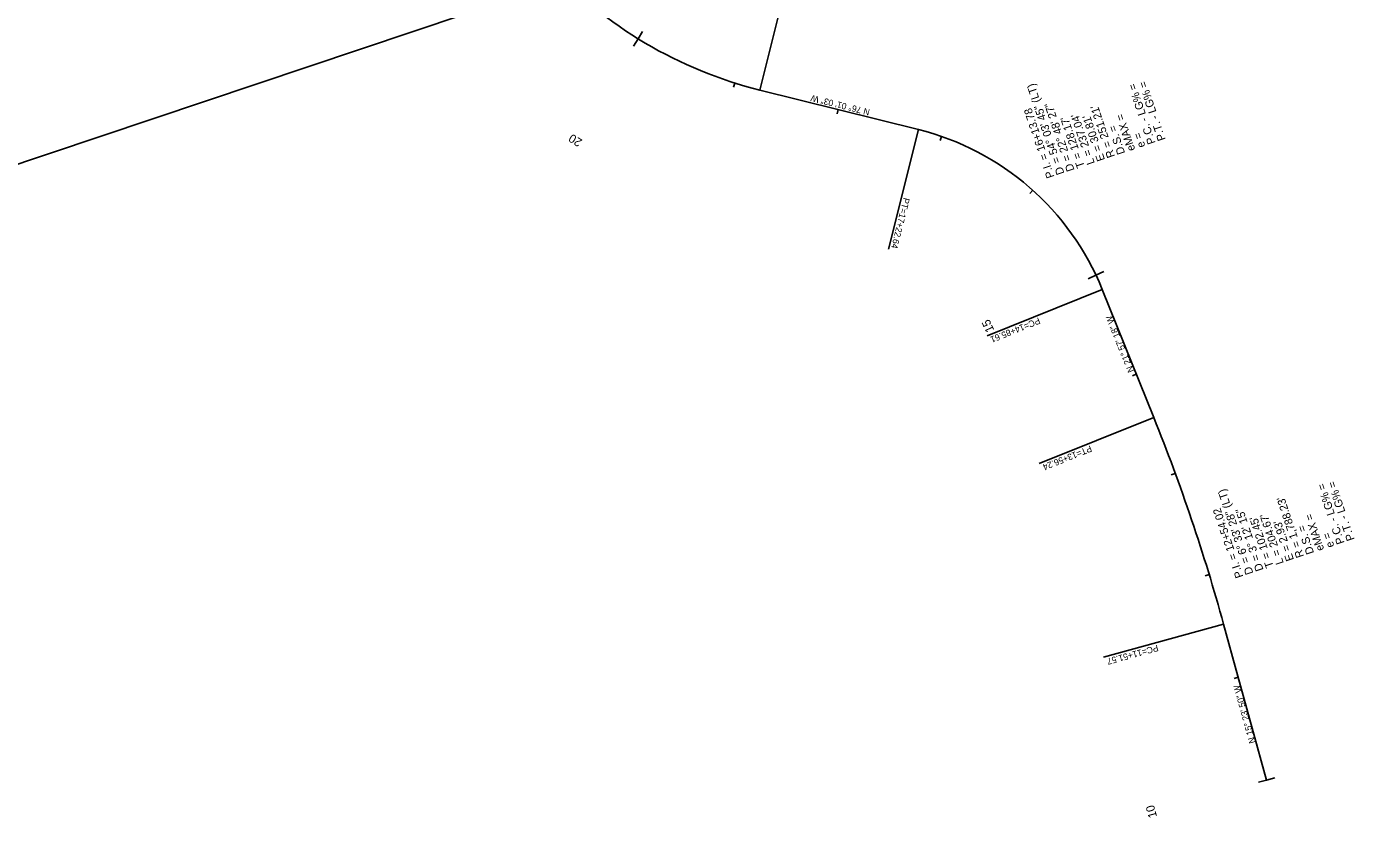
# Model space of a CAD drawing. Extents: x 1528853 to 1624411, y 1119753 to 1162242.
# Drawn here: x 1529554 to 1530799, y 1158486 to 1159228 of the extents above; entities that cross this region are included whole.
import ezdxf

# ---------------------------------------------------------------- set-up
doc = ezdxf.new("R2010")
doc.units = 0
for name, color, linetype in [('RD_HC_Cl', 7, 'Continuous'), ('RD_HC_Data', 7, 'Continuous'), ('RD_HC_Data_Tic', 7, 'Continuous'), ('RD_HC_TX_Sta50', 7, 'Continuous'), ('RD_SHT_ShtClip', 7, 'Continuous')]:
    doc.layers.add(name, color=color, linetype=linetype)

msp = doc.modelspace()

# ---------------------------------------------------------------- linework, layer by layer
at = {"layer": 'RD_HC_Cl'}
for p, q in [((1530389.9, 1159131.1), (1530241.4, 1159168.1)), ((1530610.5, 1158861.3), (1530562.2, 1158981.3)), ((1530716.3, 1158521.4), (1530676, 1158667.5))]:
    msp.add_line(p, q, dxfattribs=at)
for centre, radius, start, end in [((1530338.6, 1159558.6), 402.4, 222.8065, 256.0174), ((1530329.2, 1158887.4), 251.2, 21.955, 76.0174), ((1528952, 1158192.7), 1788.2, 15.3973, 21.955)]:
    msp.add_arc(centre, radius, start, end, dxfattribs=at)
at = {"layer": 'RD_HC_Data'}
for p, q in [((1530241.4, 1159168.1), (1530269.6, 1159281.3)), ((1530389.9, 1159131.1), (1530361.9, 1159018.9)), ((1530562.2, 1158981.3), (1530454.5, 1158937.9)), ((1530610.5, 1158861.3), (1530503.3, 1158818.1)), ((1530676, 1158667.5), (1530563.3, 1158636.5))]:
    msp.add_line(p, q, dxfattribs=at)
at = {"layer": 'RD_HC_Data_Tic'}
for p, q in [((1530127.3, 1159216.2), (1530123.1, 1159209.4)), ((1530127.3, 1159216.2), (1530131.5, 1159223)), ((1530218, 1159174.7), (1530216.8, 1159170.9)), ((1530314.8, 1159149.8), (1530313.8, 1159145.9)), ((1530411.6, 1159124.7), (1530410.3, 1159120.9)), ((1530497.1, 1159074.2), (1530494.5, 1159071.2)), ((1530556.4, 1158994.5), (1530549.2, 1158991.1)), ((1530556.4, 1158994.5), (1530563.7, 1158997.9)), ((1530594.2, 1158901.9), (1530590.5, 1158900.4)), ((1530630.7, 1158808.8), (1530627, 1158807.4)), ((1530662.6, 1158714), (1530658.7, 1158712.9)), ((1530689.7, 1158617.8), (1530685.9, 1158616.7)), ((1530716.3, 1158521.4), (1530708.6, 1158519.3)), ((1530716.3, 1158521.4), (1530724, 1158523.5))]:
    msp.add_line(p, q, dxfattribs=at)
at = {"layer": 'RD_SHT_ShtClip'}
msp.add_line((1530516.2, 1159424.4), (1529473.4, 1159074.4), dxfattribs=at)

# ---------------------------------------------------------------- texts
at = {"layer": 'RD_HC_Data'}
for s, height, rotation, p in [('    = 54%%d 03\' 45" (LT)', 7.5, 108.5287, (1530526.9, 1159090.1)), ('P.C. - LG% = ', 7.5, 108.5287, (1530612.3, 1159118.7)), ('P.T. - LG% = ', 7.5, 108.5287, (1530621.8, 1159121.9)), ('N 76%%d 01\' 03" W', 6, 166.0174, (1530344.9, 1159150)), ('P.I. = 16+13.78', 7.5, 108.5287, (1530517.5, 1159086.9)), ('D = 22%%d 48\' 27"', 7.5, 108.5287, (1530536.4, 1159093.2)), ("R = 251.21'", 7.5, 108.5287, (1530574.3, 1159106)), ("T = 128.17'", 7.5, 108.5287, (1530545.9, 1159096.4)), ("L = 237.04'", 7.5, 108.5287, (1530555.4, 1159099.6)), ("E = 30.81'", 7.5, 108.5287, (1530564.9, 1159102.8)), ('eMAX = ', 7.5, 108.5287, (1530593.3, 1159112.3)), ('D.S. = ', 7.5, 108.5287, (1530583.8, 1159109.1)), ('e = ', 7.5, 108.5287, (1530602.8, 1159115.5)), ('D', 7.5, 108.5287, (1530526.9, 1159090.1)), ('PT=17+22.64', 6, 256.0174, (1530376.1, 1159067.6)), ('PC=14+85.61', 6, 201.955, (1530502.6, 1158955.1)), ('N 21%%d 57\' 18" W', 6, 111.955, (1530592.2, 1158904.8)), ('PT=13+56.24', 6, 201.955, (1530551, 1158835.2)), ('P.T. - LG% = ', 7.5, 108.4646, (1530798.9, 1158747)), ('    = 6%%d 33\' 28" (LT)', 7.5, 108.4646, (1530704, 1158715.3)), ('P.C. - LG% = ', 7.5, 108.4646, (1530789.4, 1158743.8)), ('P.I. = 12+54.02', 7.5, 108.4646, (1530694.6, 1158712.1)), ("R = 1,788.23'", 7.5, 108.4646, (1530751.5, 1158731.1)), ('D = 3%%d 12\' 15"', 7.5, 108.4646, (1530713.5, 1158718.5)), ("T = 102.45'", 7.5, 108.4646, (1530723, 1158721.6)), ("L = 204.67'", 7.5, 108.4646, (1530732.5, 1158724.8)), ("E = 2.93'", 7.5, 108.4646, (1530742, 1158728)), ('eMAX = ', 7.5, 108.4646, (1530770.4, 1158737.5)), ('D.S. = ', 7.5, 108.4646, (1530760.9, 1158734.3)), ('e = ', 7.5, 108.4646, (1530779.9, 1158740.6)), ('D', 7.5, 108.4646, (1530704, 1158715.3)), ('PC=11+51.57', 6, 195.3973, (1530613.9, 1158648.3)), ('N 15%%d 23\' 50" W', 6, 105.3973, (1530706, 1158556.6))]:
    msp.add_text(s, height=height, rotation=rotation, dxfattribs=at).set_placement(p)
at = {"layer": 'RD_HC_TX_Sta50'}
for s, rotation, p in [('20', 148.3114, (1530075.5, 1159121.2)), ('15', 115.2381, (1530461.2, 1158943.2)), ('10', 105.3973, (1530613.7, 1158487.1))]:
    msp.add_text(s, height=8, rotation=rotation, dxfattribs=at).set_placement(p)

doc.saveas('drawing.dxf')
